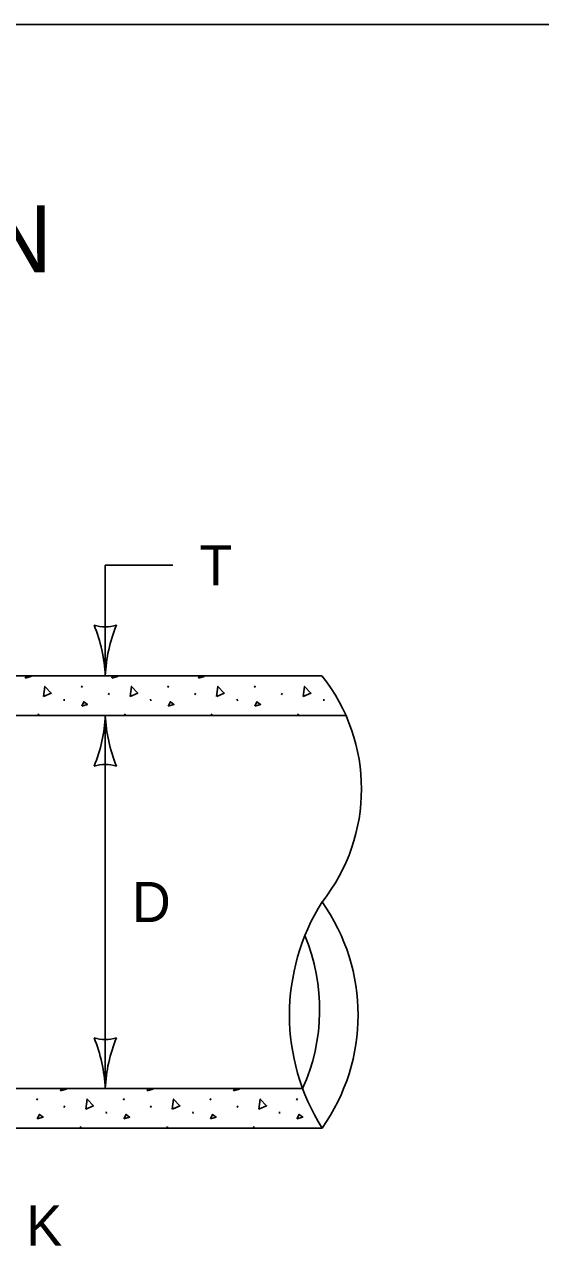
# Model space of a CAD drawing. Extents: x 49991.4 to 50043, y 49987.6 to 50011.4.
# Drawn here: x 50004.432 to 50005.204, y 49997.154 to 49998.999 of the extents above; entities that cross this region are included whole.
import ezdxf

# ---------------------------------------------------------------- set-up
doc = ezdxf.new("R2010")
doc.units = 0
for name, color, linetype in [('Level 1', 7, 'Continuous'), ('Level 2', 7, 'Continuous'), ('Level 3', 7, 'Continuous')]:
    doc.layers.add(name, color=color, linetype=linetype)

msp = doc.modelspace()

# ---------------------------------------------------------------- linework, layer by layer
at = {"layer": 'Level 1'}
for p, q in [((50004.1865, 49998.0246), (50004.877, 49998.0246)), ((50004.5167, 49998.0072), (50004.5177, 49998.0096)), ((50004.6463, 49998.0072), (50004.6473, 49998.0096)), ((50004.7759, 49998.0072), (50004.777, 49998.0096)), ((50004.4909, 49997.9896), (50004.4912, 49997.9872)), ((50004.5572, 49997.9963), (50004.5582, 49997.9987)), ((50004.6205, 49997.9896), (50004.6208, 49997.9872)), ((50004.6868, 49997.9963), (50004.6878, 49997.9987)), ((50004.7501, 49997.9896), (50004.7504, 49997.9872)), ((50004.8164, 49997.9963), (50004.8175, 49997.9987)), ((50004.8797, 49997.9896), (50004.88, 49997.9872)), ((50004.9129, 49997.9654), (50004.1233, 49997.9654)), ((50004.4518, 49997.9654), (50004.4529, 49997.9678)), ((50004.5814, 49997.9654), (50004.5825, 49997.9678)), ((50004.711, 49997.9654), (50004.7121, 49997.9678)), ((50004.8406, 49997.9654), (50004.8417, 49997.9678)), ((50004.1233, 49997.4069), (50004.848, 49997.4069)), ((50004.4503, 49997.3896), (50004.4513, 49997.392)), ((50004.4907, 49997.3787), (50004.4918, 49997.3811)), ((50004.5799, 49997.3896), (50004.5809, 49997.392)), ((50004.6204, 49997.3787), (50004.6214, 49997.3811)), ((50004.7095, 49997.3896), (50004.7105, 49997.392)), ((50004.75, 49997.3787), (50004.751, 49997.3811)), ((50004.8391, 49997.3896), (50004.8402, 49997.392)), ((50004.5541, 49997.372), (50004.5544, 49997.3696)), ((50004.6837, 49997.372), (50004.684, 49997.3696)), ((50004.8133, 49997.372), (50004.8136, 49997.3696)), ((50004.8771, 49997.3478), (50004.1865, 49997.3478)), ((50004.515, 49997.3478), (50004.5161, 49997.3502)), ((50004.6446, 49997.3478), (50004.6457, 49997.3502)), ((50004.7742, 49997.3478), (50004.7753, 49997.3502))]:
    msp.add_line(p, q, dxfattribs=at)
msp.add_lwpolyline([(49999.3835, 49998.9992), (50016.7501, 49998.9992), (50016.7501, 49987.7988), (49999.3835, 49987.7988)], close=True, dxfattribs=at)
for points in [[(50004.4328, 49998.0209), (50004.4345, 49998.0245)], [(50004.44, 49998.0245), (50004.4413, 49998.0236), (50004.4328, 49998.0209)], [(50004.5624, 49998.0209), (50004.5641, 49998.0245)], [(50004.5697, 49998.0245), (50004.5709, 49998.0236), (50004.5624, 49998.0209)], [(50004.692, 49998.0209), (50004.6937, 49998.0245)], [(50004.6993, 49998.0245), (50004.7005, 49998.0236), (50004.692, 49998.0209)], [(50004.46, 49997.9935), (50004.4621, 49998.0088), (50004.4716, 49997.9989), (50004.4602, 49997.9936)], [(50004.5896, 49997.9935), (50004.5917, 49998.0088), (50004.6012, 49997.9989), (50004.5898, 49997.9936)], [(50004.7192, 49997.9935), (50004.7213, 49998.0088), (50004.7308, 49997.9989), (50004.7194, 49997.9936)], [(50004.8488, 49997.9935), (50004.8509, 49998.0088), (50004.8604, 49997.9989), (50004.849, 49997.9936)], [(50004.5172, 49997.9793), (50004.5204, 49997.9859), (50004.5257, 49997.9819), (50004.5172, 49997.9793)], [(50004.6468, 49997.9793), (50004.65, 49997.9859), (50004.6553, 49997.9819), (50004.6468, 49997.9793)], [(50004.7764, 49997.9793), (50004.7796, 49997.9859), (50004.785, 49997.9819), (50004.7764, 49997.9793)], [(50004.4855, 49997.4033), (50004.4872, 49997.4069)], [(50004.4928, 49997.4069), (50004.494, 49997.406), (50004.4855, 49997.4033)], [(50004.6151, 49997.4033), (50004.6168, 49997.4069)], [(50004.6224, 49997.4069), (50004.6236, 49997.406), (50004.6151, 49997.4033)], [(50004.7447, 49997.4033), (50004.7464, 49997.4069)], [(50004.752, 49997.4069), (50004.7532, 49997.406), (50004.7447, 49997.4033)], [(50004.5232, 49997.3759), (50004.5253, 49997.3912), (50004.5348, 49997.3813), (50004.5234, 49997.376)], [(50004.6528, 49997.3759), (50004.6549, 49997.3912), (50004.6644, 49997.3813), (50004.653, 49997.376)], [(50004.7824, 49997.3759), (50004.7845, 49997.3912), (50004.794, 49997.3813), (50004.7826, 49997.376)], [(50004.4508, 49997.3617), (50004.454, 49997.3683), (50004.4593, 49997.3643), (50004.4508, 49997.3617)], [(50004.5804, 49997.3617), (50004.5836, 49997.3683), (50004.5889, 49997.3643), (50004.5804, 49997.3617)], [(50004.71, 49997.3617), (50004.7132, 49997.3683), (50004.7185, 49997.3643), (50004.71, 49997.3617)], [(50004.8396, 49997.3617), (50004.8428, 49997.3683), (50004.8482, 49997.3643), (50004.8396, 49997.3617)]]:
    msp.add_lwpolyline(points, dxfattribs=at)
for centre, radius, start, end in [((50004.6644, 49997.8553), 0.2718, 321.5118, 38.5186), ((50005.146, 49997.517), 0.3176, 147.818, 212.1849), ((50004.6388, 49997.517), 0.2923, 324.6332, 35.3668), ((50004.5866, 49997.5252), 0.287, 335.6613, 22.6629)]:
    msp.add_arc(centre, radius, start, end, dxfattribs=at)
at = {"layer": 'Level 3'}
for p, q in [((50004.5526, 49998.1901), (50004.5526, 49998.0246)), ((50004.5526, 49998.1901), (50004.6536, 49998.1901)), ((50004.5526, 49997.9654), (50004.5526, 49997.4069))]:
    msp.add_line(p, q, dxfattribs=at)
for centre, radius, start, end in [((50004.5526, 49998.1528), 0.0548, 252.1388, 287.8612), ((50004.3199, 49998.0131), 0.233, 2.8273, 22.0772), ((50004.7747, 49998.0155), 0.2223, 157.456, 177.6395), ((50004.3305, 49997.9746), 0.2223, 337.456, 357.6395), ((50004.7853, 49997.9769), 0.233, 182.8273, 202.0772), ((50004.5526, 49997.8372), 0.0548, 72.1388, 107.8612), ((50004.5526, 49997.5351), 0.0548, 252.1388, 287.8612), ((50004.3199, 49997.3954), 0.233, 2.8273, 22.0772), ((50004.7747, 49997.3978), 0.2223, 157.456, 177.6395)]:
    msp.add_arc(centre, radius, start, end, dxfattribs=at)

# ---------------------------------------------------------------- texts
at = {"layer": 'Level 2'}
for s, height, p in [('INLET AND OUTLET TRANSITION', 0.1, (50002.3625, 49998.6287)), ('T', 0.06, (50004.6936, 49998.1601)), ('D', 0.06, (50004.5926, 49997.6562)), ('K', 0.06, (50004.4344, 49997.172))]:
    msp.add_text(s, height=height, dxfattribs=at).set_placement(p)

doc.saveas('drawing.dxf')
